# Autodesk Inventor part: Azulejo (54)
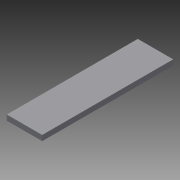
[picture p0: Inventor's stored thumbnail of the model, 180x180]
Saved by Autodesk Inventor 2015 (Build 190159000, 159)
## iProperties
Created: 2015-04
Part Number: Azulejo (54)
Material: Genérico
Document SubType Name: Modeling
Designer: Felipe
Density: 1 g/cm^3
Appearance: Padrão
Author: Felipe
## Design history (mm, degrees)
sketch "Sketch1"
  geometry: L1 (285.105, 1636.833)-(285.105, 156.833); L2 (685.105, 156.833)-(685.105, 1636.833); L3 (685.105, 1636.833)-(285.105, 1636.833); L4 (285.105, 156.833)-(685.105, 156.833); L5 (1765.105, 156.833)-(765.105, 156.833); L6 (765.105, 156.833)-(765.105, 1636.833); L7 (765.105, 1636.833)-(1765.105, 1636.833); L8 (1765.105, 1636.833)-(1765.105, 156.833); 1 further point
  constraints: 16 end point
extrude "Extrusion1" new body sketch "Sketch1" distance "d0" = 60; taper "d1" = 0 deg
body "Solid1"
